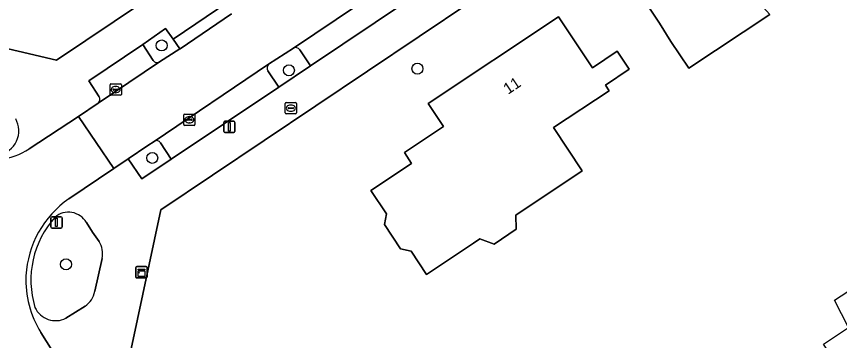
# Model space of a CAD drawing. Extents: x 161347 to 161881, y 382161 to 382804.
# Drawn here: x 161527.2 to 161600.2, y 382558.6 to 382587.4 of the extents above; entities that cross this region are included whole.
import ezdxf

# ---------------------------------------------------------------- set-up
doc = ezdxf.new("R2010")
doc.units = 0
for name, color, linetype in [('IMGEO_Boom', 7, 'Continuous'), ('IMGEO_Erf', 7, 'Continuous'), ('IMGEO_Groenvoorziening', 7, 'Continuous'), ('IMGEO_Kast', 7, 'Continuous'), ('IMGEO_Kolk', 7, 'Continuous'), ('IMGEO_Lichtmast', 7, 'Continuous'), ('IMGEO_Pand', 7, 'Continuous'), ('IMGEO_Pand_nummerreeks', 7, 'Continuous'), ('IMGEO_Pand_vergunning_verleend', 7, 'Continuous'), ('IMGEO_Parkeervlak_open', 7, 'Continuous'), ('IMGEO_Rijbaan_lokaal_open', 7, 'Continuous'), ('IMGEO_Rioolput', 7, 'Continuous'), ('IMGEO_Voetpad_open', 7, 'Continuous')]:
    doc.layers.add(name, color=color, linetype=linetype)

msp = doc.modelspace()

# ---------------------------------------------------------------- linework, layer by layer
at = {"layer": 'IMGEO_Boom'}
for centre in [(161540.067, 382584.789), (161551.354, 382582.584), (161562.763, 382582.729), (161539.224, 382574.803), (161531.573, 382565.347)]:
    msp.add_circle(centre, 0.489, dxfattribs=at)
at = {"layer": 'IMGEO_Erf'}
for points in [[(161467.626, 382669.884), (161470.191, 382665.995), (161471.419, 382664.034), (161492.823, 382629.848), (161494.69, 382626.794), (161500, 382618.564), (161504.473, 382611.274), (161506.241, 382608.392), (161519.986, 382585.99), (161530.719, 382583.477), (161556.508, 382600.797), (161574.373, 382612.676), (161577.471, 382614.736), (161612.276, 382637.879), (161612.356, 382637.679), (161628.452, 382648.518)], [(161572.092, 382591.77), (161539.981, 382570.178), (161537.341, 382557.85), (161565.95, 382511.235), (161572.292, 382501.343), (161572.851, 382501.493), (161573.727, 382500), (161581.489, 382486.772), (161593.113, 382483.942), (161618.484, 382500), (161639.588, 382513.357), (161643.126, 382515.61), (161643.533, 382515.936), (161628.206, 382532.98), (161623.055, 382540.753), (161664.71, 382578.468), (161661.6, 382581.894), (161665.593, 382585.519), (161669.295, 382588.879)]]:
    msp.add_lwpolyline(points, dxfattribs=at)
for points in [[(161586.843, 382582.771), (161585.26, 382585.149), (161584.249, 382586.775), (161582.497, 382589.408), (161588.702, 382593.537), (161592.026, 382589.802), (161594.028, 382587.553)], [(161569.571, 382567.153), (161568.313, 382567.605), (161567.737, 382567.222), (161563.574, 382564.452), (161562.19, 382566.534), (161561.251, 382566.737), (161559.828, 382568.877), (161560.002, 382569.822), (161558.617, 382571.903), (161562.24, 382574.313), (161561.598, 382575.277), (161565.07, 382577.587), (161563.713, 382579.627), (161575.294, 382587.333), (161578.3, 382582.816), (161580.499, 382584.28), (161581.56, 382582.687), (161579.439, 382581.276), (161579.772, 382580.776), (161574.836, 382577.492), (161577.395, 382573.647), (161571.505, 382569.729), (161571.536, 382568.46)]]:
    msp.add_lwpolyline(points, close=True, dxfattribs=at)
at = {"layer": 'IMGEO_Groenvoorziening'}
for points in [[(161541.067, 382585.364), (161540.41, 382586.303), (161538.38, 382584.881), (161539.297, 382583.454)], [(161539.857, 382583.327), (161541.677, 382584.488), (161541.067, 382585.364)], [(161549.492, 382582.534), (161550.455, 382581.099), (161553.267, 382582.995), (161552.318, 382584.391)], [(161551.753, 382584.552), (161549.551, 382583.116)], [(161539.403, 382576.271), (161538.819, 382575.91), (161537.081, 382574.722), (161538.305, 382572.954), (161540.9, 382574.692), (161539.956, 382576.13)], [(161534.509, 382567.389), (161533.931, 382568.208), (161533.376, 382569.068)], [(161534.117, 382562.952), (161534.767, 382565.87)], [(161531.562, 382560.564), (161533.263, 382561.648)]]:
    msp.add_lwpolyline(points, dxfattribs=at)
for centre, radius, start, end in [((161551.948, 382584.164), 0.434, 31.51085, 116.67874), ((161539.645, 382583.692), 0.422, 214.38219, 300.06235), ((161549.9, 382582.787), 0.48, 136.69265, 211.73023), ((161525.223, 382577.22), 2.163, 279.79948, 29.53282), ((161539.616, 382575.953), 0.383, 27.53408, 123.85774), ((161531.787, 382568.151), 1.834, 29.97903, 130.41472), ((161536.859, 382563.94), 8.405, 138.14806, 196.83958), ((161532.738, 382566.307), 2.075, 347.84811, 31.43112), ((161532.202, 382563.274), 1.942, 303.11147, 350.44631), ((161530.649, 382562.38), 2.033, 205.49728, 296.69715)]:
    msp.add_arc(centre, radius, start, end, dxfattribs=at)
at = {"layer": 'IMGEO_Kast'}
for p, q in [((161537.768, 382564.218), (161537.768, 382565.059)), ((161537.768, 382565.059), (161537.768, 382564.218)), ((161537.843, 382565.143), (161538.684, 382565.143)), ((161538.684, 382565.143), (161537.843, 382565.143)), ((161538.768, 382565.068), (161538.768, 382564.227)), ((161538.768, 382564.227), (161538.768, 382565.068)), ((161538.693, 382564.143), (161537.852, 382564.143)), ((161537.852, 382564.143), (161538.693, 382564.143))]:
    msp.add_line(p, q, dxfattribs=at)
for points in [[(161537.963, 382564.933), (161538.563, 382564.933), (161538.563, 382564.848), (161537.963, 382564.848), (161537.963, 382564.933)], [(161537.963, 382564.758), (161538.563, 382564.758), (161538.563, 382564.269), (161537.963, 382564.269), (161537.963, 382564.758)]]:
    msp.add_lwpolyline(points, dxfattribs=at)
msp.add_circle((161538.047, 382564.607), 0.0377, dxfattribs=at)
for centre, start, end in [((161537.846, 382565.065), 92.4484, 184.28452), ((161537.846, 382565.065), 92.4484, 184.28452), ((161538.69, 382565.065), 2.4484, 94.28452), ((161538.69, 382565.065), 2.4484, 94.28452), ((161537.846, 382564.221), 182.4484, 274.28452), ((161537.846, 382564.221), 182.4484, 274.28452), ((161538.69, 382564.221), 272.4484, 4.28452), ((161538.69, 382564.221), 272.4484, 4.28452)]:
    msp.add_arc(centre, 0.0779, start, end, dxfattribs=at)
at = {"layer": 'IMGEO_Kolk'}
for p, q in [((161535.48, 382580.448), (161535.48, 382581.3)), ((161535.555, 382581.374), (161536.407, 382581.374)), ((161536.481, 382581.3), (161536.481, 382580.448)), ((161535.739, 382580.868), (161535.739, 382580.88)), ((161536.177, 382580.831), (161535.779, 382580.831)), ((161535.782, 382580.917), (161536.18, 382580.917)), ((161535.991, 382580.594), (161535.966, 382580.594)), ((161535.968, 382581.154), (161535.993, 382581.154)), ((161536.223, 382580.88), (161536.223, 382580.868)), ((161536.407, 382580.374), (161535.555, 382580.374)), ((161542.017, 382577.766), (161542.017, 382578.618)), ((161542.092, 382578.692), (161542.944, 382578.692)), ((161542.505, 382578.472), (161542.53, 382578.472)), ((161543.018, 382578.618), (161543.018, 382577.766)), ((161542.944, 382577.692), (161542.092, 382577.692)), ((161542.276, 382578.186), (161542.276, 382578.198)), ((161542.714, 382578.149), (161542.316, 382578.149)), ((161542.319, 382578.235), (161542.717, 382578.235)), ((161542.528, 382577.912), (161542.503, 382577.912)), ((161542.76, 382578.198), (161542.76, 382578.186))]:
    msp.add_line(p, q, dxfattribs=at)
for points in [[(161535.48, 382580.448), (161535.48, 382581.3)], [(161535.555, 382581.374), (161536.407, 382581.374)], [(161536.481, 382581.3), (161536.481, 382580.448)], [(161536.407, 382580.374), (161535.555, 382580.374)], [(161542.017, 382577.766), (161542.017, 382578.618)], [(161542.092, 382578.692), (161542.944, 382578.692)], [(161543.018, 382578.618), (161543.018, 382577.766)], [(161542.944, 382577.692), (161542.092, 382577.692)]]:
    msp.add_lwpolyline(points, dxfattribs=at)
for centre, radius, start, end in [((161535.557, 382581.298), 0.0765, 91.55205, 178.44795), ((161535.557, 382581.298), 0.0765, 91.55205, 178.44795), ((161536.405, 382581.298), 0.0765, 1.55205, 88.44795), ((161536.405, 382581.298), 0.0765, 1.55205, 88.44795), ((161535.779, 382580.877), 0.0403, 85.87752, 175.75265), ((161535.776, 382580.867), 0.0366, 178.93798, 274.71019), ((161536.18, 382580.874), 0.043, 264.86636, 352.45326), ((161536.184, 382580.879), 0.0386, 1.73085, 96.63898), ((161535.557, 382580.45), 0.0765, 181.55205, 268.44795), ((161535.557, 382580.45), 0.0765, 181.55205, 268.44795), ((161536.405, 382580.45), 0.0765, 271.55205, 358.44795), ((161536.405, 382580.45), 0.0765, 271.55205, 358.44795), ((161542.094, 382578.616), 0.0765, 91.55205, 178.44795), ((161542.094, 382578.616), 0.0765, 91.55205, 178.44795), ((161542.942, 382578.616), 0.0765, 1.55205, 88.44795), ((161542.942, 382578.616), 0.0765, 1.55205, 88.44795), ((161542.094, 382577.768), 0.0765, 181.55205, 268.44795), ((161542.094, 382577.768), 0.0765, 181.55205, 268.44795), ((161542.316, 382578.195), 0.0403, 85.87752, 175.75265), ((161542.313, 382578.185), 0.0366, 178.93798, 274.71019), ((161542.717, 382578.192), 0.043, 264.86636, 352.45326), ((161542.721, 382578.197), 0.0386, 1.73085, 96.63898), ((161542.942, 382577.768), 0.0765, 271.55205, 358.44795), ((161542.942, 382577.768), 0.0765, 271.55205, 358.44795)]:
    msp.add_arc(centre, radius, start, end, dxfattribs=at)
for centre, major_axis, ratio, start_param, end_param in [((161535.967, 382580.874), (-0.387, 0.002), 0.722429, 4.712389, 7.853982), ((161535.992, 382580.874), (-0.39, 0.002), 0.717154, 1.570796, 4.712389), ((161542.504, 382578.192), (-0.387, 0.002), 0.722429, 4.712389, 7.853982), ((161542.529, 382578.192), (-0.39, 0.002), 0.717154, 1.570796, 4.712389)]:
    msp.add_ellipse(centre, major_axis=major_axis, ratio=ratio, start_param=start_param, end_param=end_param, dxfattribs=at)
at = {"layer": 'IMGEO_Lichtmast'}
for p, q in [((161545.577, 382577.16), (161545.577, 382577.96)), ((161545.577, 382577.96), (161545.577, 382577.16)), ((161545.677, 382578.06), (161546.467, 382578.06)), ((161546.467, 382578.06), (161545.677, 382578.06)), ((161546.567, 382577.96), (161546.567, 382577.16)), ((161546.567, 382577.16), (161546.567, 382577.96)), ((161546.467, 382577.06), (161545.677, 382577.06)), ((161545.677, 382577.06), (161546.467, 382577.06)), ((161530.228, 382568.677), (161530.228, 382569.477)), ((161530.228, 382569.477), (161530.228, 382568.677)), ((161530.328, 382569.577), (161531.118, 382569.577)), ((161531.118, 382569.577), (161530.328, 382569.577)), ((161531.218, 382569.477), (161531.218, 382568.677)), ((161531.218, 382568.677), (161531.218, 382569.477)), ((161531.118, 382568.577), (161530.328, 382568.577)), ((161530.328, 382568.577), (161531.118, 382568.577))]:
    msp.add_line(p, q, dxfattribs=at)
for points in [[(161545.997, 382577.935), (161546.147, 382577.935), (161546.147, 382577.185), (161545.997, 382577.185), (161545.997, 382577.935)], [(161530.648, 382569.452), (161530.798, 382569.452), (161530.798, 382568.702), (161530.648, 382568.702), (161530.648, 382569.452)]]:
    msp.add_lwpolyline(points, dxfattribs=at)
for centre, start, end in [((161545.677, 382577.96), 90, 180), ((161545.677, 382577.96), 90, 180), ((161546.467, 382577.96), 0, 90), ((161546.467, 382577.96), 360, 90), ((161545.677, 382577.16), 180, 270), ((161545.677, 382577.16), 180, 270), ((161546.467, 382577.16), 270, 0), ((161546.467, 382577.16), 270, 0), ((161530.328, 382569.477), 90, 180), ((161530.328, 382569.477), 90, 180), ((161531.118, 382569.477), 0, 90), ((161531.118, 382569.477), 360, 90), ((161530.328, 382568.677), 180, 270), ((161530.328, 382568.677), 180, 270), ((161531.118, 382568.677), 270, 0), ((161531.118, 382568.677), 270, 0)]:
    msp.add_arc(centre, 0.1, start, end, dxfattribs=at)
at = {"layer": 'IMGEO_Pand'}
for points in [[(161585.26, 382585.149), (161586.843, 382582.771), (161594.028, 382587.553), (161592.026, 382589.802), (161588.702, 382593.537), (161582.497, 382589.408), (161584.249, 382586.775)], [(161568.313, 382567.605), (161569.571, 382567.153), (161571.536, 382568.46), (161571.505, 382569.729), (161577.395, 382573.647), (161574.836, 382577.492), (161579.772, 382580.776), (161579.439, 382581.276), (161581.56, 382582.687), (161580.499, 382584.28), (161578.3, 382582.816), (161575.294, 382587.333), (161563.713, 382579.627), (161565.07, 382577.587), (161561.598, 382575.277), (161562.24, 382574.313), (161558.617, 382571.903), (161560.002, 382569.822), (161559.828, 382568.877), (161561.251, 382566.737), (161562.19, 382566.534), (161563.574, 382564.452), (161567.737, 382567.222)]]:
    msp.add_lwpolyline(points, close=True, dxfattribs=at)
at = {"layer": 'IMGEO_Pand_vergunning_verleend'}
msp.add_lwpolyline([(161598.788, 382558.262), (161601.01, 382559.736), (161599.78, 382562.167), (161600.967, 382562.944), (161603.149, 382561.186), (161605.103, 382562.508), (161608.602, 382559.648), (161600.908, 382555.108)], close=True, dxfattribs=at)
at = {"layer": 'IMGEO_Parkeervlak_open'}
for points in [[(161566.828, 382594.718), (161551.753, 382584.552)], [(161552.318, 382584.391), (161553.267, 382582.995), (161567.696, 382592.692)], [(161539.297, 382583.454), (161538.38, 382584.881), (161533.593, 382581.65), (161534.509, 382580.242)], [(161534.428, 382579.67), (161539.857, 382583.327)], [(161549.551, 382583.116), (161539.403, 382576.271)], [(161550.455, 382581.099), (161549.492, 382582.534)], [(161539.956, 382576.13), (161540.9, 382574.692), (161550.455, 382581.099)]]:
    msp.add_lwpolyline(points, dxfattribs=at)
for centre, radius, start, end in [((161551.948, 382584.164), 0.434, 31.51085, 116.67874), ((161539.645, 382583.692), 0.422, 214.38219, 300.06235), ((161549.9, 382582.787), 0.48, 136.69265, 211.73023), ((161534.138, 382580.003), 0.442, 311.09559, 32.78447), ((161539.616, 382575.953), 0.383, 27.53408, 123.85774)]:
    msp.add_arc(centre, radius, start, end, dxfattribs=at)
at = {"layer": 'IMGEO_Rijbaan_lokaal_open'}
for points in [[(161546.269, 382587.605), (161541.693, 382584.498), (161541.677, 382584.488), (161539.857, 382583.327), (161534.428, 382579.67), (161532.667, 382578.479), (161535.802, 382573.856), (161537.081, 382574.722), (161538.819, 382575.91), (161539.403, 382576.271), (161549.551, 382583.116), (161551.753, 382584.552), (161566.828, 382594.718)], [(161531.835, 382571.172), (161535.802, 382573.856), (161532.667, 382578.479), (161528.3, 382575.604)], [(161531.997, 382555.059), (161529.325, 382559.309)]]:
    msp.add_lwpolyline(points, dxfattribs=at)
for centre, radius, start, end in [((161525.194, 382580.255), 5.593, 274.96798, 303.74054), ((161536.899, 382563.859), 8.895, 124.70399, 176.93523), ((161536.974, 382563.983), 8.964, 177.74893, 211.42598)]:
    msp.add_arc(centre, radius, start, end, dxfattribs=at)
at = {"layer": 'IMGEO_Rioolput'}
for p, q in [((161551.024, 382578.795), (161551.024, 382579.647)), ((161551.099, 382579.721), (161551.951, 382579.721)), ((161551.283, 382579.215), (161551.283, 382579.227)), ((161551.721, 382579.178), (161551.323, 382579.178)), ((161551.326, 382579.264), (161551.724, 382579.264)), ((161551.512, 382579.501), (161551.537, 382579.501)), ((161551.767, 382579.227), (161551.767, 382579.215)), ((161552.025, 382579.647), (161552.025, 382578.795)), ((161551.951, 382578.721), (161551.099, 382578.721)), ((161551.535, 382578.941), (161551.51, 382578.941))]:
    msp.add_line(p, q, dxfattribs=at)
for points in [[(161551.024, 382578.795), (161551.024, 382579.647)], [(161551.099, 382579.721), (161551.951, 382579.721)], [(161552.025, 382579.647), (161552.025, 382578.795)], [(161551.951, 382578.721), (161551.099, 382578.721)]]:
    msp.add_lwpolyline(points, dxfattribs=at)
for centre, radius, start, end in [((161551.101, 382579.645), 0.0765, 91.55205, 178.44795), ((161551.101, 382579.645), 0.0765, 91.55205, 178.44795), ((161551.323, 382579.224), 0.0403, 85.87752, 175.75265), ((161551.32, 382579.214), 0.0366, 178.93798, 274.71019), ((161551.724, 382579.221), 0.043, 264.86636, 352.45326), ((161551.728, 382579.226), 0.0386, 1.73085, 96.63898), ((161551.949, 382579.645), 0.0765, 1.55205, 88.44795), ((161551.949, 382579.645), 0.0765, 1.55205, 88.44795), ((161551.101, 382578.797), 0.0765, 181.55205, 268.44795), ((161551.101, 382578.797), 0.0765, 181.55205, 268.44795), ((161551.949, 382578.797), 0.0765, 271.55205, 358.44795), ((161551.949, 382578.797), 0.0765, 271.55205, 358.44795)]:
    msp.add_arc(centre, radius, start, end, dxfattribs=at)
for centre, major_axis, ratio, start_param, end_param in [((161551.511, 382579.221), (-0.387, 0.002), 0.722429, 4.712389, 7.853982), ((161551.536, 382579.221), (-0.39, 0.002), 0.717154, 1.570796, 4.712389)]:
    msp.add_ellipse(centre, major_axis=major_axis, ratio=ratio, start_param=start_param, end_param=end_param, dxfattribs=at)
at = {"layer": 'IMGEO_Voetpad_open'}
for points in [[(161633.531, 382651.891), (161632.827, 382651.824), (161628.452, 382648.518), (161612.356, 382637.679), (161612.276, 382637.879), (161577.471, 382614.736), (161574.373, 382612.676), (161556.508, 382600.797), (161530.719, 382583.477), (161519.986, 382585.99), (161514.869, 382582.227), (161517.208, 382578.534)], [(161636.042, 382640.978), (161637.263, 382639.172), (161635.101, 382637.794), (161625.023, 382631.053), (161624.388, 382631.946), (161620.048, 382629.035), (161620.647, 382628.172), (161617.655, 382626.128), (161608.366, 382619.905), (161604.861, 382617.547), (161590.935, 382608.278), (161587.772, 382606.172), (161587.144, 382607.09), (161574.859, 382598.875), (161575.536, 382597.897), (161570.33, 382594.467), (161567.696, 382592.692), (161553.267, 382582.995), (161550.455, 382581.099), (161540.9, 382574.692), (161538.305, 382572.954), (161537.081, 382574.722), (161535.802, 382573.856), (161531.835, 382571.172)], [(161539.981, 382570.178), (161572.092, 382591.77), (161588.954, 382602.772), (161591.014, 382604.147), (161626.724, 382627.988), (161642.272, 382638.554), (161645.871, 382640.073)], [(161540.41, 382586.303), (161541.067, 382585.364), (161546.022, 382588.682), (161545.38, 382589.578), (161555.001, 382596.043), (161557.659, 382597.826), (161558.295, 382596.893), (161562.64, 382599.822), (161562.017, 382600.769), (161566.681, 382603.875), (161567.302, 382602.987), (161572.313, 382606.29), (161571.539, 382607.403), (161574.77, 382609.585), (161575.54, 382608.454), (161581.017, 382612.127), (161580.541, 382612.811)], [(161546.346, 382588.179), (161546.022, 382588.682), (161541.067, 382585.364), (161541.677, 382584.488), (161541.693, 382584.498), (161546.269, 382587.605)], [(161534.509, 382580.242), (161533.593, 382581.65), (161538.38, 382584.881), (161540.41, 382586.303)], [(161528.3, 382575.604), (161532.667, 382578.479), (161534.428, 382579.67)], [(161533.289, 382554.218), (161533.602, 382554.172), (161537.341, 382557.85), (161539.981, 382570.178)], [(161533.376, 382569.068), (161533.931, 382568.208), (161534.509, 382567.389)], [(161534.767, 382565.87), (161534.117, 382562.952)], [(161533.263, 382561.648), (161531.562, 382560.564)], [(161529.325, 382559.309), (161531.997, 382555.059)]]:
    msp.add_lwpolyline(points, dxfattribs=at)
for centre, radius, start, end in [((161534.138, 382580.003), 0.442, 311.09559, 32.78447), ((161525.223, 382577.22), 2.163, 279.79948, 29.53282), ((161525.194, 382580.255), 5.593, 274.96798, 303.74054), ((161536.899, 382563.859), 8.895, 124.70399, 176.93523), ((161531.787, 382568.151), 1.834, 29.97903, 130.41472), ((161536.859, 382563.94), 8.405, 138.14806, 196.83958), ((161532.738, 382566.307), 2.075, 347.84811, 31.43112), ((161536.974, 382563.983), 8.964, 177.74893, 211.42598), ((161532.202, 382563.274), 1.942, 303.11147, 350.44631), ((161530.649, 382562.38), 2.033, 205.49728, 296.69715)]:
    msp.add_arc(centre, radius, start, end, dxfattribs=at)

# ---------------------------------------------------------------- texts
at = {"layer": 'IMGEO_Pand_nummerreeks'}
msp.add_text('11', height=1, rotation=33.63835, dxfattribs=at).set_placement((161570.803, 382580.405))

doc.saveas('drawing.dxf')
